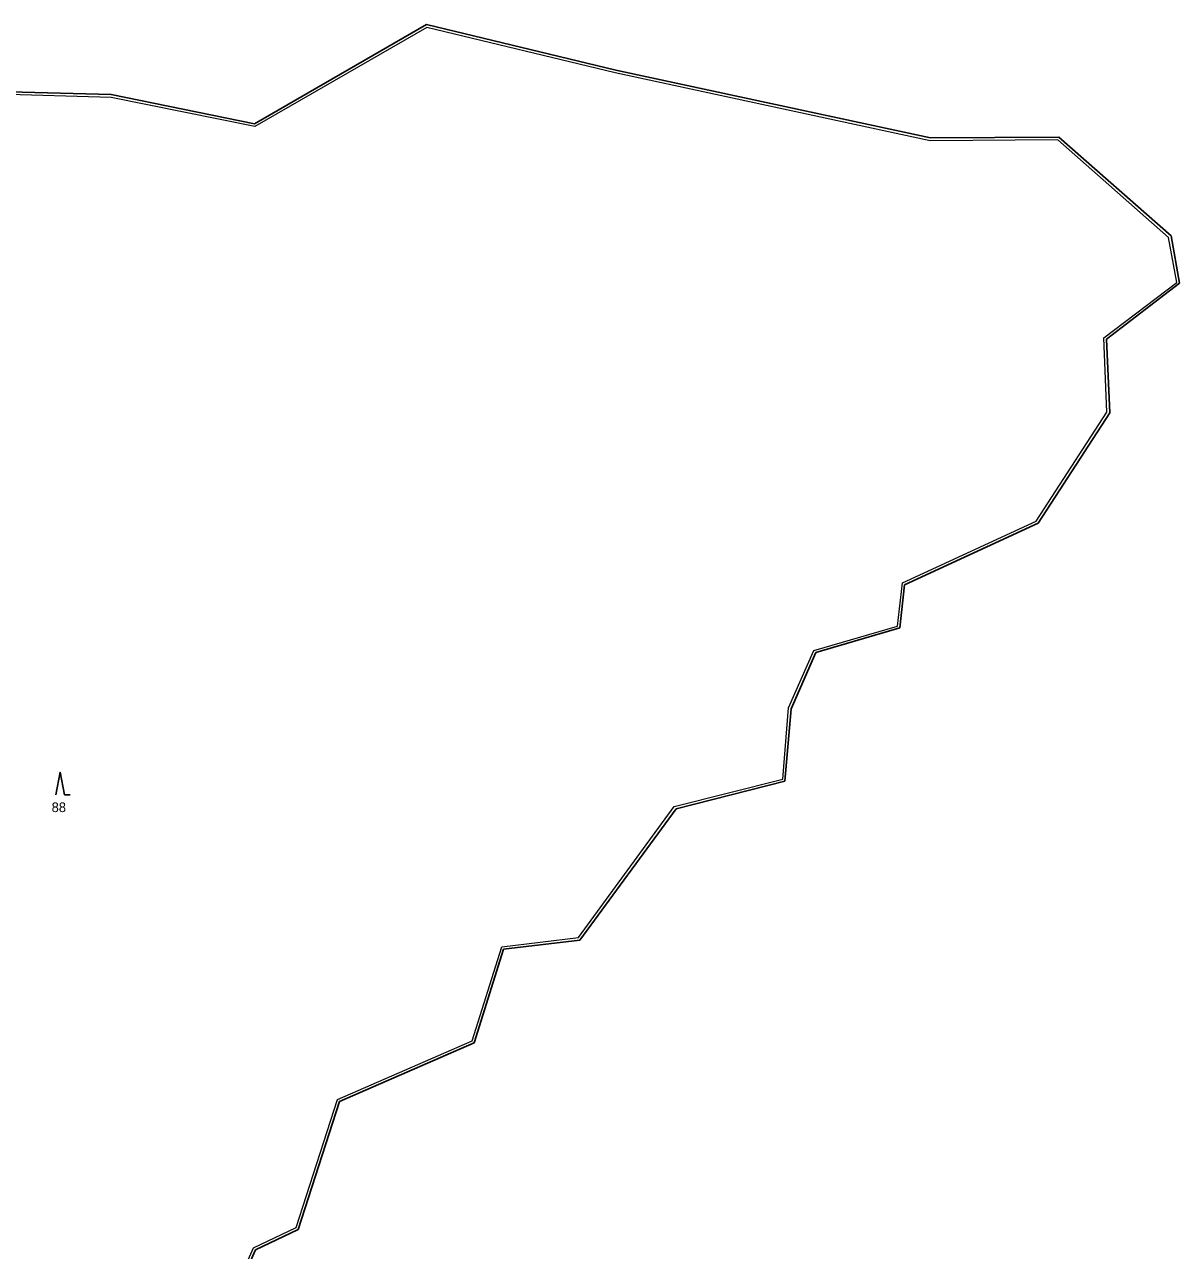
# Model space of a CAD drawing. Extents: x -653193 to -651624, y -1092017 to -1090260.
# Drawn here: x -652620.8 to -652417.2, y -1090476.3 to -1090260.2 of the extents above; entities that cross this region are included whole.
import ezdxf
from ezdxf.enums import TextEntityAlignment as Align

# ---------------------------------------------------------------- set-up
doc = ezdxf.new("R2010")
doc.units = 0
doc.header["$LTSCALE"] = 0.68
for name, color, linetype, lineweight in [('1', 7, 'Continuous', 25), ('3', 7, 'Continuous', 25), ('4', 7, 'Continuous', 13)]:
    doc.layers.add(name, color=color, linetype=linetype, lineweight=lineweight)
doc.layers.add('2', color=7, linetype='Continuous')

msp = doc.modelspace()

# ---------------------------------------------------------------- linework, layer by layer
at = {"layer": '1'}
for p, q in [((-652549.91, -1090260.22), (-652580.26, -1090277.72)), ((-652516.52, -1090268.27), (-652549.91, -1090260.22)), ((-652461.05, -1090280.2), (-652516.52, -1090268.27)), ((-652605.48, -1090272.57), (-652633.51, -1090271.81)), ((-652580.26, -1090277.72), (-652605.48, -1090272.57)), ((-652438.46, -1090280.06), (-652461.05, -1090280.2)), ((-652418.66, -1090297.49), (-652438.46, -1090280.06)), ((-652417.17, -1090305.83), (-652418.66, -1090297.49)), ((-652430.04, -1090315.67), (-652417.17, -1090305.83)), ((-652429.46, -1090328.65), (-652430.04, -1090315.67)), ((-652442.11, -1090348.1), (-652429.46, -1090328.65)), ((-652465.64, -1090359), (-652442.11, -1090348.1)), ((-652466.5, -1090366.57), (-652465.64, -1090359)), ((-652481.28, -1090370.9), (-652466.5, -1090366.57)), ((-652485.63, -1090380.87), (-652481.28, -1090370.9)), ((-652486.77, -1090393.59), (-652485.63, -1090380.87)), ((-652505.93, -1090398.46), (-652486.77, -1090393.59)), ((-652522.91, -1090421.63), (-652505.93, -1090398.46)), ((-652536.35, -1090423.2), (-652522.91, -1090421.63)), ((-652541.52, -1090439.73), (-652536.35, -1090423.2)), ((-652565.26, -1090450.05), (-652541.52, -1090439.73)), ((-652572.53, -1090472.64), (-652565.26, -1090450.05)), ((-652580.08, -1090476.22), (-652572.53, -1090472.64)), ((-652590.93, -1090500.73), (-652580.08, -1090476.22))]:
    msp.add_line(p, q, dxfattribs=at)
at = {"layer": '3'}
msp.add_line((-652613.76, -1090396.03), (-652612.764, -1090396.03), dxfattribs=at)
msp.add_lwpolyline([(-652613.76, -1090396.03), (-652614.51, -1090392.03), (-652615.26, -1090396.03)], dxfattribs=at)
at = {"layer": '4'}
for p, q in [((-652549.87, -1090260.72), (-652580.2, -1090278.22)), ((-652516.63, -1090268.76), (-652549.87, -1090260.72)), ((-652461.11, -1090280.7), (-652516.63, -1090268.76)), ((-652605.52, -1090273.07), (-652633.35, -1090272.28)), ((-652580.2, -1090278.22), (-652605.52, -1090273.07)), ((-652438.6, -1090280.54), (-652461.11, -1090280.7)), ((-652419.09, -1090297.75), (-652438.6, -1090280.54)), ((-652417.65, -1090305.67), (-652419.09, -1090297.75)), ((-652430.48, -1090315.44), (-652417.65, -1090305.67)), ((-652429.95, -1090328.56), (-652430.48, -1090315.44)), ((-652442.46, -1090347.74), (-652429.95, -1090328.56)), ((-652465.99, -1090358.64), (-652442.46, -1090347.74)), ((-652466.88, -1090366.25), (-652465.99, -1090358.64)), ((-652481.65, -1090370.57), (-652466.88, -1090366.25)), ((-652486.09, -1090380.67), (-652481.65, -1090370.57)), ((-652487.12, -1090393.24), (-652486.09, -1090380.67)), ((-652506.24, -1090398.07), (-652487.12, -1090393.24)), ((-652523.1, -1090421.17), (-652506.24, -1090398.07)), ((-652536.66, -1090422.81), (-652523.1, -1090421.17)), ((-652541.86, -1090439.37), (-652536.66, -1090422.81)), ((-652565.6, -1090449.69), (-652541.86, -1090439.37)), ((-652572.87, -1090472.27), (-652565.6, -1090449.69)), ((-652580.44, -1090475.87), (-652572.87, -1090472.27)), ((-652591.23, -1090500.33), (-652580.44, -1090475.87))]:
    msp.add_line(p, q, dxfattribs=at)

# ---------------------------------------------------------------- texts
at = {"layer": '2'}
msp.add_text('88', height=1.7, dxfattribs=at).set_placement((-652614.739, -1090399.045), align=Align.CENTER)

doc.saveas('drawing.dxf')
